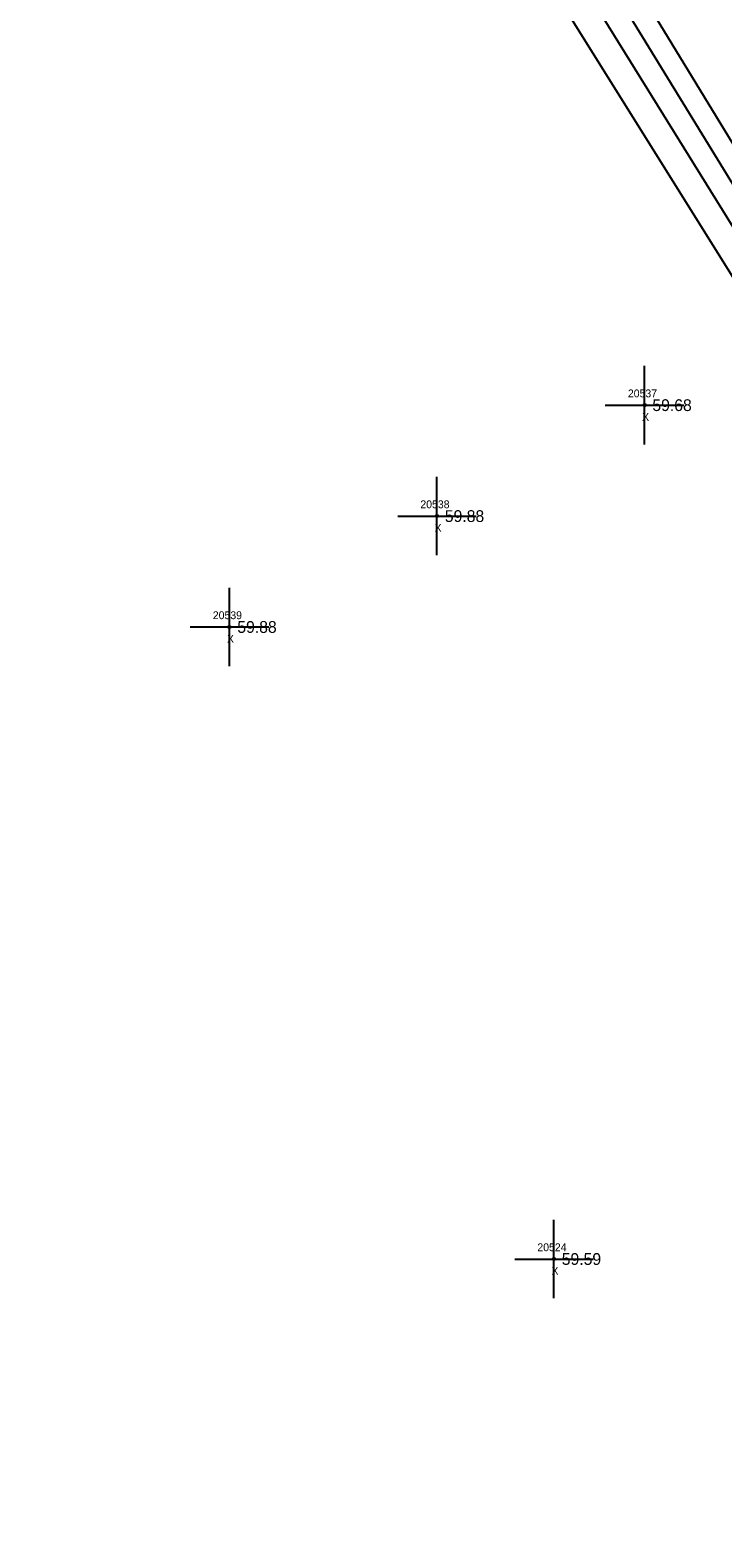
# Model space of a CAD drawing. Extents: x 2396547 to 2397655, y 770185 to 772649.
# Drawn here: x 2397251.2 to 2397339.4, y 770555.1 to 770747.4 of the extents above; entities that cross this region are included whole.
import ezdxf

# ---------------------------------------------------------------- set-up
doc = ezdxf.new("R2010")
doc.units = 0
for name, color, linetype in [('RD_EX_H2O', 7, 'Continuous'), ('RD_EX_Misc', 7, 'Continuous'), ('RD_EX_Misc_txCode', 7, 'Continuous'), ('RD_EX_Road', 7, 'Continuous'), ('RD_EX_TX_Misc_ELEV', 7, 'Continuous'), ('RD_SMD_Locator', 7, 'Continuous')]:
    doc.layers.add(name, color=color, linetype=linetype)

msp = doc.modelspace()

# ---------------------------------------------------------------- linework, layer by layer
at = {"layer": 'RD_EX_H2O'}
for points in [[(2397432.83, 770561.85), (2397399.16, 770627.27), (2397350.75, 770711.42), (2397293.36, 770805.09), (2397257.48, 770863.23)], [(2397428.38, 770563.87), (2397397.36, 770626.2), (2397348.29, 770710.09), (2397290.43, 770803.51), (2397255.11, 770861.71)], [(2397432.83, 770561.85), (2397426.86, 770559.56), (2397394.23, 770624.59), (2397345.55, 770708.21), (2397287.31, 770801.51), (2397251.15, 770859.33)]]:
    msp.add_lwpolyline(points, dxfattribs=at)
at = {"layer": 'RD_EX_Misc'}
for p, q in [((2397329.45, 770694.6), (2397329.45, 770704.6)), ((2397324.45, 770699.6), (2397334.45, 770699.6)), ((2397303, 770680.45), (2397303, 770690.45)), ((2397298, 770685.45), (2397308, 770685.45)), ((2397276.55, 770666.3), (2397276.55, 770676.3)), ((2397271.55, 770671.3), (2397281.55, 770671.3)), ((2397317.9, 770585.67), (2397317.9, 770595.67)), ((2397312.9, 770590.67), (2397322.9, 770590.67))]:
    msp.add_line(p, q, dxfattribs=at)
at = {"layer": 'RD_EX_Road'}
msp.add_lwpolyline([(2397553.19, 770205.48), (2397535.12, 770280.96), (2397517, 770349.24), (2397493.4, 770422.78), (2397467.13, 770492.9), (2397441.16, 770551.74), (2397436.66, 770561.67), (2397402.21, 770629.28), (2397353, 770712.83), (2397296, 770806.32), (2397260.16, 770864.73)], dxfattribs=at)
at = {"layer": 'RD_SMD_Locator'}
for centre in [(2397329.45, 770699.6), (2397303, 770685.45), (2397276.55, 770671.3), (2397317.9, 770590.67)]:
    msp.add_circle(centre, 0.15, dxfattribs=at)

# ---------------------------------------------------------------- texts
at = {"layer": 'RD_EX_Misc_txCode'}
for s, p in [('20537', (2397327.33, 770700.6)), ('X', (2397329.14, 770697.6)), ('20538', (2397300.88, 770686.45)), ('X', (2397302.69, 770683.45)), ('20539', (2397274.43, 770672.3)), ('X', (2397276.23, 770669.3)), ('20524', (2397315.79, 770591.67)), ('X', (2397317.59, 770588.67))]:
    msp.add_text(s, height=1, dxfattribs=at).set_placement(p)
at = {"layer": 'RD_EX_TX_Misc_ELEV'}
for s, p in [('59.68', (2397330.45, 770698.85)), ('59.88', (2397304, 770684.7)), ('59.88', (2397277.55, 770670.55)), ('59.59', (2397318.9, 770589.92))]:
    msp.add_text(s, height=1.5, dxfattribs=at).set_placement(p)

doc.saveas('drawing.dxf')
